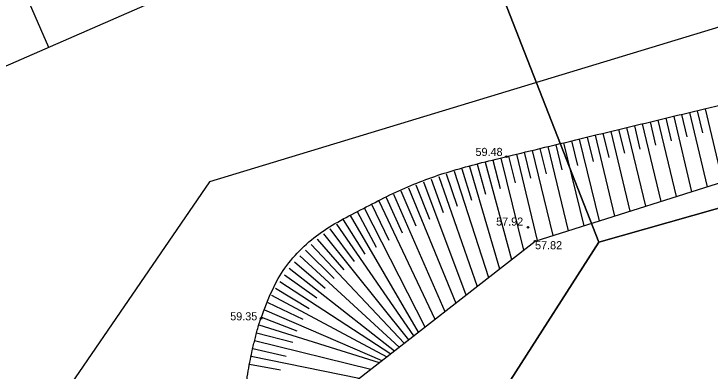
# Model space of a CAD drawing. Extents: x 616607 to 617499, y 408385 to 409695.
# Drawn here: x 616694.34 to 616737.38, y 408514.38 to 408536.47 of the extents above; entities that cross this region are included whole.
import ezdxf

# ---------------------------------------------------------------- set-up
doc = ezdxf.new("R2010")
doc.units = 0
for name, color, linetype in [('HIDG_GRAV_####_####_#', 7, 'Continuous'), ('RAMI_PLAN_####_TKST_#', 7, 'Continuous'), ('RAMI_UZMR_####_####_#', 7, 'Continuous'), ('RELJ_AATZ_####_TKST_#', 7, 'Continuous'), ('RELJ_ELEM_####_####_#', 7, 'Continuous'), ('RELJ_NOGA_####_####_#', 7, 'Continuous'), ('ROBZ_IERR_####_####_#', 7, 'Continuous'), ('ROBZ_UZMR_####_####_#', 7, 'Continuous')]:
    doc.layers.add(name, color=color, linetype=linetype)

# ---------------------------------------------------------------- blocks, each defined once
blk = doc.blocks.new('PKT')
at = {"layer": 'RELJ_ELEM_####_####_#'}
blk.add_circle((0, 0), 0.05, dxfattribs=at)

msp = doc.modelspace()

# ---------------------------------------------------------------- linework, layer by layer
at = {"layer": 'HIDG_GRAV_####_####_#'}
msp.add_lwpolyline([(616765.45, 408526.57), (616717.618, 408497.675), (616716.98, 408493.818), (616722.239, 408486.737), (616723.371, 408480.51), (616720.037, 408475.133), (616696.755, 408470.663), (616689.283, 408471.969), (616682.791, 408476.247), (616681.206, 408477.551), (616679.98, 408480.284), (616680.025, 408480.874), (616680.52, 408481.458), (616702.717, 408488.625), (616709.142, 408492.712), (616711.432, 408499.757), (616715.088, 408513.471), (616726.56, 408522.413), (616768.796, 408535.775)], dxfattribs=at)
at = {"layer": 'RAMI_PLAN_####_TKST_#'}
for p, q in [((616691.167, 408546.586), (616696.484, 408534.403)), ((616710.322, 408540.443), (616614.799, 408498.746))]:
    msp.add_line(p, q, dxfattribs=at)
at = {"layer": 'RAMI_UZMR_####_####_#'}
msp.add_lwpolyline([(617191.828, 409115.62), (617145.545, 408952.8), (617072.809, 408766.141), (616965.332, 408652.076), (616939.432, 408594.661), (616924.839, 408592.467), (616706.433, 408526.081), (616666.426, 408467.691)], dxfattribs=at)
at = {"layer": 'RELJ_NOGA_####_####_#'}
for p, q in [((616736.101, 408530.366), (616737.19, 408525.776)), ((616736.101, 408530.366), (616736.102, 408530.365)), ((616736.588, 408530.481), (616736.912, 408529.115)), ((616736.588, 408530.481), (616736.588, 408530.481)), ((616737.074, 408530.597), (616738.146, 408526.078)), ((616737.074, 408530.597), (616737.075, 408530.596)), ((616734.156, 408529.902), (616735.287, 408525.174)), ((616734.156, 408529.902), (616734.156, 408529.901)), ((616734.642, 408530.018), (616734.978, 408528.61)), ((616734.642, 408530.018), (616734.642, 408530.018)), ((616735.129, 408530.135), (616736.24, 408525.475)), ((616735.129, 408530.135), (616735.129, 408530.134)), ((616735.615, 408530.25), (616735.945, 408528.863)), ((616735.615, 408530.25), (616735.615, 408530.25)), ((616732.697, 408529.553), (616733.045, 408528.103)), ((616732.697, 408529.553), (616732.697, 408529.552)), ((616733.183, 408529.669), (616734.334, 408524.872)), ((616733.183, 408529.669), (616733.184, 408529.668)), ((616733.67, 408529.786), (616734.012, 408528.357)), ((616733.67, 408529.786), (616733.67, 408529.786)), ((616730.753, 408529.084), (616731.112, 408527.595)), ((616730.753, 408529.084), (616730.753, 408529.084)), ((616731.239, 408529.202), (616732.428, 408524.269)), ((616731.239, 408529.202), (616731.239, 408529.201)), ((616731.725, 408529.319), (616732.079, 408527.849)), ((616731.725, 408529.319), (616731.725, 408529.318)), ((616732.211, 408529.436), (616733.381, 408524.571)), ((616732.211, 408529.436), (616732.211, 408529.435)), ((616728.809, 408528.615), (616729.179, 408527.085)), ((616728.809, 408528.615), (616728.809, 408528.614)), ((616729.295, 408528.732), (616730.519, 408523.665)), ((616729.295, 408528.732), (616729.295, 408528.731)), ((616729.781, 408528.85), (616730.146, 408527.34)), ((616729.781, 408528.85), (616729.781, 408528.849)), ((616730.267, 408528.967), (616731.473, 408523.967)), ((616730.267, 408528.967), (616730.267, 408528.966)), ((616727.351, 408528.262), (616728.61, 408523.061)), ((616727.351, 408528.262), (616727.351, 408528.261)), ((616727.837, 408528.38), (616728.212, 408526.829)), ((616727.837, 408528.38), (616727.837, 408528.379)), ((616728.323, 408528.497), (616729.565, 408523.364)), ((616728.323, 408528.497), (616728.323, 408528.496)), ((616725.407, 408527.791), (616726.698, 408522.457)), ((616725.407, 408527.791), (616725.407, 408527.79)), ((616725.893, 408527.909), (616726.278, 408526.319)), ((616725.893, 408527.909), (616725.893, 408527.909)), ((616726.379, 408528.027), (616727.654, 408522.759)), ((616726.379, 408528.027), (616726.379, 408528.026)), ((616726.865, 408528.144), (616727.245, 408526.574)), ((616726.865, 408528.144), (616726.865, 408528.144)), ((616723.951, 408527.431), (616724.411, 408525.675)), ((616723.951, 408527.431), (616723.951, 408527.431)), ((616724.435, 408527.555), (616725.853, 408521.862)), ((616724.435, 408527.555), (616724.436, 408527.554)), ((616724.921, 408527.674), (616725.32, 408526.024)), ((616724.921, 408527.674), (616724.921, 408527.673)), ((616722.027, 408526.887), (616722.622, 408524.949)), ((616722.027, 408526.887), (616722.027, 408526.886)), ((616722.505, 408527.031), (616724.369, 408520.705)), ((616722.505, 408527.031), (616722.506, 408527.03)), ((616722.986, 408527.17), (616723.506, 408525.312)), ((616722.986, 408527.17), (616722.986, 408527.169)), ((616723.468, 408527.303), (616725.1, 408521.275)), ((616723.468, 408527.303), (616723.468, 408527.302)), ((616721.074, 408526.582), (616721.749, 408524.574)), ((616721.074, 408526.582), (616721.074, 408526.581)), ((616721.55, 408526.737), (616723.674, 408520.163)), ((616721.55, 408526.737), (616721.55, 408526.736)), ((616719.661, 408526.08), (616722.29, 408519.085)), ((616719.661, 408526.08), (616719.661, 408526.079)), ((616720.13, 408526.253), (616720.879, 408524.181)), ((616720.13, 408526.253), (616720.13, 408526.253)), ((616720.601, 408526.42), (616722.975, 408519.618)), ((616720.601, 408526.42), (616720.601, 408526.419)), ((616718.73, 408525.715), (616721.654, 408518.589)), ((616718.73, 408525.715), (616718.73, 408525.714)), ((616719.194, 408525.901), (616720.026, 408523.78)), ((616719.194, 408525.901), (616719.194, 408525.9)), ((616717.809, 408525.325), (616720.992, 408518.072)), ((616717.809, 408525.325), (616717.809, 408525.324)), ((616718.268, 408525.523), (616719.183, 408523.365)), ((616718.268, 408525.523), (616718.268, 408525.523)), ((616716.899, 408524.911), (616720.373, 408517.59)), ((616716.899, 408524.911), (616716.899, 408524.91)), ((616717.352, 408525.121), (616718.352, 408522.934)), ((616717.352, 408525.121), (616717.353, 408525.121)), ((616716.001, 408524.471), (616719.752, 408517.106)), ((616716.001, 408524.471), (616716.001, 408524.47)), ((616716.448, 408524.694), (616717.527, 408522.486)), ((616716.448, 408524.694), (616716.448, 408524.694)), ((616715.121, 408523.997), (616719.34, 408516.785)), ((616715.121, 408523.997), (616715.121, 408523.996)), ((616715.557, 408524.241), (616716.735, 408522.038)), ((616715.557, 408524.241), (616715.557, 408524.241)), ((616714.277, 408523.461), (616719.037, 408516.549)), ((616714.277, 408523.461), (616714.277, 408523.46)), ((616714.694, 408523.737), (616716.035, 408521.61)), ((616714.694, 408523.737), (616714.694, 408523.736)), ((616713.87, 408523.17), (616715.375, 408521.149)), ((616713.87, 408523.17), (616713.87, 408523.17)), ((616713.474, 408522.865), (616718.743, 408516.32)), ((616713.474, 408522.865), (616713.474, 408522.864)), ((616712.718, 408522.211), (616718.459, 408516.098)), ((616712.718, 408522.211), (616712.718, 408522.21)), ((616713.09, 408522.545), (616714.737, 408520.639)), ((616713.09, 408522.545), (616713.09, 408522.545)), ((616712.359, 408521.863), (616714.146, 408520.101)), ((616712.359, 408521.863), (616712.359, 408521.863)), ((616712.013, 408521.502), (616718.156, 408515.862)), ((616712.013, 408521.502), (616712.014, 408521.501)), ((616711.682, 408521.127), (616713.577, 408519.511)), ((616711.682, 408521.127), (616711.682, 408521.127)), ((616711.366, 408520.74), (616717.866, 408515.636)), ((616711.366, 408520.74), (616711.367, 408520.739)), ((616711.066, 408520.34), (616713.075, 408518.905)), ((616711.066, 408520.34), (616711.066, 408520.339)), ((616710.783, 408519.928), (616717.635, 408515.456)), ((616710.783, 408519.928), (616710.783, 408519.927)), ((616710.517, 408519.504), (616712.602, 408518.251)), ((616710.517, 408519.504), (616710.517, 408519.504)), ((616710.269, 408519.07), (616717.388, 408515.264)), ((616710.269, 408519.07), (616710.27, 408519.069)), ((616710.041, 408518.625), (616712.207, 408517.587)), ((616710.041, 408518.625), (616710.041, 408518.625)), ((616709.833, 408518.17), (616717.091, 408515.032)), ((616709.833, 408518.17), (616709.834, 408518.17)), ((616709.646, 408517.707), (616711.838, 408516.872)), ((616709.646, 408517.707), (616709.646, 408517.707)), ((616709.484, 408517.234), (616716.923, 408514.901)), ((616709.484, 408517.234), (616709.485, 408517.234)), ((616709.348, 408516.753), (616711.586, 408516.171)), ((616709.348, 408516.753), (616709.348, 408516.753)), ((616709.226, 408516.268), (616716.41, 408514.501)), ((616709.226, 408516.268), (616709.227, 408516.268)), ((616709.109, 408515.782), (616711.176, 408515.302)), ((616709.109, 408515.782), (616709.109, 408515.782)), ((616709.002, 408515.293), (616715.689, 408513.939)), ((616709.002, 408515.293), (616709.003, 408515.293)), ((616708.907, 408514.803), (616710.819, 408514.448)), ((616708.907, 408514.803), (616708.907, 408514.803))]:
    msp.add_line(p, q, dxfattribs=at)
msp.add_open_spline([(616975.731, 408606.41), (616971.71, 408604.144), (616967.689, 408601.878), (616963.668, 408599.612), (616962.341, 408598.864), (616961.192, 408597.791), (616960.311, 408596.511), (616959.39, 408595.173), (616958.675, 408593.776), (616958.002, 408592.329), (616957.302, 408590.825), (616956.736, 408589.272), (616956.015, 408587.778), (616955.313, 408586.324), (616954.582, 408584.882), (616953.626, 408583.572), (616952.496, 408582.025), (616951.261, 408580.593), (616950.022, 408579.143), (616948.785, 408577.695), (616947.537, 408576.278), (616946.22, 408574.895), (616945.626, 408574.271), (616944.957, 408573.742), (616944.225, 408573.278), (616943.451, 408572.788), (616942.648, 408572.387), (616941.804, 408572.051), (616941, 408571.73), (616940.2, 408571.414), (616939.368, 408571.187), (616938.69, 408571.002), (616938.005, 408570.852), (616937.329, 408570.663), (616918.615, 408565.441), (616899.903, 408560.204), (616881.253, 408554.75), (616874.57, 408552.796), (616867.991, 408550.484), (616861.269, 408548.669), (616855.483, 408547.106), (616849.688, 408545.577), (616843.9, 408544.023), (616838.111, 408542.469), (616832.323, 408540.916), (616826.537, 408539.352), (616816.497, 408536.637), (616806.51, 408533.737), (616796.541, 408530.774), (616791.553, 408529.292), (616786.584, 408527.751), (616781.609, 408526.226), (616776.622, 408524.697), (616771.656, 408523.11), (616766.688, 408521.515), (616762.607, 408520.204), (616758.677, 408518.521), (616754.775, 408516.687), (616750.921, 408514.875), (616747.341, 408512.653), (616743.915, 408510.109), (616740.341, 408507.454), (616736.942, 408504.677), (616733.801, 408501.555), (616732.131, 408499.895), (616730.49, 408498.223), (616728.926, 408496.468), (616728.114, 408495.556), (616727.318, 408494.632), (616726.518, 408493.709), (616725.695, 408492.76), (616724.91, 408491.864), (616724.122, 408490.803), (616723.665, 408490.187), (616723.18, 408489.459), (616723.332, 408488.764), (616723.537, 408487.829), (616723.949, 408486.896), (616724.213, 408485.954), (616724.975, 408483.236), (616725.742, 408480.486), (616726.381, 408477.738), (616726.631, 408476.667), (616726.554, 408475.507), (616726.221, 408474.429), (616726.043, 408473.855), (616725.77, 408473.346), (616725.415, 408472.86), (616725.226, 408472.602), (616725.032, 408472.37), (616724.813, 408472.14), (616724.582, 408471.898), (616724.347, 408471.683), (616724.071, 408471.48), (616723.783, 408471.268), (616723.475, 408471.091), (616723.13, 408471.039), (616722.812, 408470.991), (616722.494, 408470.986), (616722.176, 408470.982), (616721.543, 408470.975), (616720.901, 408471.154), (616720.278, 408471.02), (616716.569, 408470.219), (616712.93, 408469.339), (616709.261, 408468.478), (616707.424, 408468.047), (616705.589, 408467.613), (616703.751, 408467.182), (616701.927, 408466.754), (616700.076, 408466.424), (616698.236, 408466.115), (616695.42, 408465.64), (616692.315, 408465.565), (616689.691, 408467.073), (616684.319, 408470.158), (616679.892, 408473.486), (616675.008, 408476.777), (616674.831, 408476.896), (616674.652, 408477.012), (616674.483, 408477.14), (616674.175, 408477.376), (616674.46, 408477.978), (616674.696, 408478.288), (616675.427, 408479.251), (616676.165, 408480.2), (616676.939, 408481.135), (616677.893, 408482.289), (616678.812, 408483.429), (616679.848, 408484.532), (616681.078, 408485.839), (616682.698, 408486.726), (616684.412, 408487.237), (616686.183, 408487.764), (616687.958, 408488.143), (616689.768, 408488.401), (616691.642, 408488.668), (616693.528, 408488.826), (616695.398, 408489.116), (616696.323, 408489.26), (616697.239, 408489.444), (616698.155, 408489.647), (616699.054, 408489.848), (616699.912, 408490.166), (616700.785, 408490.476), (616703.122, 408491.305), (616705.613, 408491.942), (616707.248, 408494.043), (616707.429, 408494.275), (616707.474, 408494.537), (616707.552, 408494.798), (616707.628, 408495.051), (616707.711, 408495.3), (616707.761, 408495.559), (616707.86, 408496.068), (616707.943, 408496.577), (616707.977, 408497.092), (616708.044, 408498.12), (616708.108, 408499.147), (616708.168, 408500.175), (616708.254, 408501.63), (616708.34, 408503.085), (616708.414, 408504.54), (616708.488, 408505.998), (616708.403, 408507.461), (616708.436, 408508.92), (616708.468, 408510.38), (616708.539, 408511.837), (616708.686, 408513.293), (616708.76, 408514.026), (616708.887, 408514.749), (616709.039, 408515.47), (616709.116, 408515.834), (616709.208, 408516.193), (616709.297, 408516.554), (616709.387, 408516.92), (616709.487, 408517.278), (616709.619, 408517.635), (616710.681, 408520.51), (616712.959, 408522.898), (616715.736, 408524.335), (616718.688, 408525.863), (616721.668, 408526.887), (616724.792, 408527.643), (616730.078, 408528.922), (616735.359, 408530.207), (616740.655, 408531.436), (616749.901, 408533.581), (616759.244, 408535.317), (616768.413, 408537.779), (616798.7, 408545.91), (616828.618, 408555.288), (616858.746, 408563.964), (616877.646, 408569.406), (616896.581, 408574.731), (616915.501, 408580.089), (616916.131, 408580.267), (616916.803, 408580.127), (616917.44, 408580.402), (616917.832, 408580.571), (616918.181, 408580.992), (616918.136, 408581.394), (616918.071, 408581.969), (616918.005, 408582.544), (616917.94, 408583.119), (616917.87, 408583.733), (616917.799, 408584.347), (616917.73, 408584.96), (616917.674, 408585.454), (616917.97, 408585.948), (616918.384, 408586.3), (616918.906, 408586.742), (616919.445, 408586.959), (616920.02, 408587.218), (616920.568, 408587.465), (616921.093, 408587.698), (616921.676, 408587.899), (616922.792, 408588.284), (616923.918, 408588.529), (616925.044, 408588.565), (616925.938, 408588.594), (616926.854, 408588.454), (616927.734, 408588.123), (616928.677, 408587.768), (616929.526, 408587.359), (616930.432, 408586.999), (616931.324, 408586.645), (616932.223, 408586.313), (616933.127, 408585.998), (616933.97, 408585.704), (616934.935, 408585.706), (616935.807, 408585.922), (616937.564, 408586.355), (616939.443, 408587.201), (616940.422, 408588.724), (616944.438, 408594.972), (616948.27, 408601.228), (616952.11, 408607.531)], degree=3, dxfattribs=at)
at = {"layer": 'ROBZ_IERR_####_####_#'}
for points in [[(617055.284, 408797.783), (617087.528, 408757.04), (616999.181, 408676.019), (616968.565, 408608.405), (616958.517, 408604.593), (616940.576, 408582.801), (616889.795, 408568.012), (616805.459, 408543.657), (616730.494, 408522.344), (616717.135, 408556.579)], [(616717.135, 408556.579), (616730.494, 408522.344), (616708.653, 408488.203), (616688.046, 408471.498), (616671.463, 408478.715), (616654.855, 408488.541)]]:
    msp.add_lwpolyline(points, dxfattribs=at)
at = {"layer": 'ROBZ_UZMR_####_####_#'}
msp.add_lwpolyline([(616704.998, 408460.626), (616695.309, 408466.84), (616688.046, 408471.498), (616708.653, 408488.203), (616730.494, 408522.344), (616805.459, 408543.657), (616889.795, 408568.012), (616940.576, 408582.801), (616958.517, 408604.593), (616968.565, 408608.405), (616974.837, 408605.827), (616993.227, 408598.268)], dxfattribs=at)

# ---------------------------------------------------------------- block references
at = {"layer": 'RELJ_ELEM_####_####_#'}
for p in [(616724.792, 408527.643), (616726.12, 408523.275), (616726.56, 408522.413), (616709.619, 408517.635)]:
    msp.add_blockref('PKT', p, dxfattribs=at)

# ---------------------------------------------------------------- texts
at = {"layer": 'RELJ_AATZ_####_TKST_#'}
for s, p in [('59.48', (616722.878, 408527.685)), ('57.92', (616724.153, 408523.376)), ('57.82', (616726.56, 408521.913)), ('59.35', (616707.715, 408517.517))]:
    msp.add_text(s, height=0.5, dxfattribs=at).set_placement(p)

doc.saveas('drawing.dxf')
